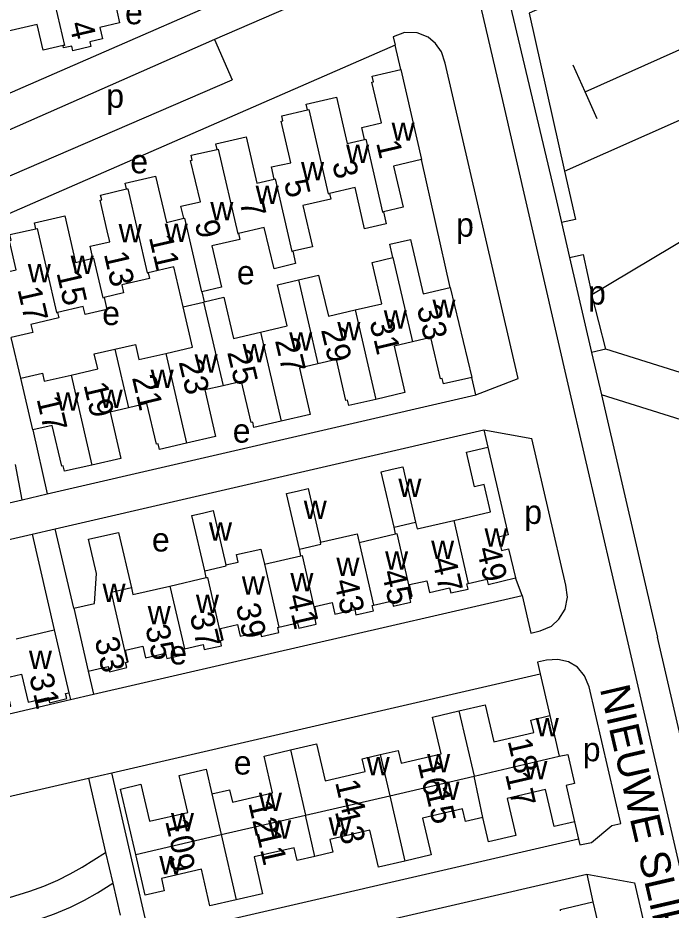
# Model space of a CAD drawing. Extents: x 155696 to 157795, y 382328 to 384028.
# Drawn here: x 157175.4 to 157284.9, y 383450.5 to 383600.1 of the extents above; entities that cross this region are included whole.
import ezdxf

# ---------------------------------------------------------------- set-up
doc = ezdxf.new("R2010")
doc.units = 0
for name, color, linetype in [('BLT_Basislijn', 7, 'Continuous'), ('BLT_Bebouwing', 7, 'Continuous'), ('BLT_Centroide', 7, 'Continuous'), ('BLT_Huisnummer', 7, 'Continuous'), ('BLT_Huisnummer_ tussenligend', 7, 'Continuous'), ('BLT_Onderverdeling_panden', 7, 'Continuous'), ('BLT_Straatnaam', 7, 'Continuous')]:
    doc.layers.add(name, color=color, linetype=linetype)

msp = doc.modelspace()

# ---------------------------------------------------------------- linework, layer by layer
at = {"layer": 'BLT_Basislijn'}
for p, q in [((157232.55, 383607.09), (157208.37, 383596.51)), ((157270.5, 383587.69), (157297.93, 383600.04)), ((157208.37, 383596.51), (157155.06, 383573.01)), ((157208.37, 383596.51), (157211.33, 383589.75)), ((157270.5, 383587.69), (157268.48, 383592.17)), ((157157.85, 383566.64), (157211.33, 383589.75)), ((157272.52, 383583.21), (157270.5, 383587.69)), ((157271.63, 383553.72), (157323.49, 383584.65)), ((157247.91, 383554.89), (157243.07, 383576.35)), ((157273.96, 383544.53), (157271.63, 383553.72)), ((157175.89, 383539.68), (157174.29, 383546.5)), ((157252.2, 383536.88), (157259.27, 383539.61)), ((157253.55, 383531.03), (157261.58, 383529.58)), ((157176.12, 383519.3), (157180.33, 383520.27)), ((157177.78, 383513.53), (157181.68, 383514.43)), ((157259.96, 383503.26), (157258.82, 383506.18)), ((157188.1, 383486.66), (157259.96, 383503.26)), ((157293.18, 383450.53), (157282.62, 383496.27)), ((157187.18, 383490.53), (157188.1, 383486.66)), ((157183.92, 383486.93), (157184.23, 383485.77)), ((157116.22, 383470.06), (157184.23, 383485.77)), ((157184.23, 383485.77), (157188.1, 383486.66)), ((157187.23, 383472.61), (157191.13, 383473.51)), ((157270.77, 383456.49), (157271.83, 383451.83))]:
    msp.add_line(p, q, dxfattribs=at)
for points in [[(157254.58, 383616.41), (157265.55, 383570.16), (157266.56, 383565.8)], [(157234.4, 383613.91), (157165.65, 383583.84), (157164.91, 383587.02)], [(157308.66, 383597.41), (157292.13, 383614.53), (157261.12, 383600.89), (157267.05, 383574.43)], [(157343.69, 383231.89), (157341.11, 383231.75), (157339.69, 383232.44), (157338.68, 383233.57), (157337.75, 383235.4), (157324.13, 383294.34), (157315.46, 383331.86), (157299.82, 383399.57), (157277.88, 383494.57), (157267.86, 383537.93), (157256.53, 383587.01), (157250.87, 383611.5)], [(157259.27, 383539.61), (157247.04, 383592.51), (157246.42, 383594.43), (157245.44, 383595.85), (157244.22, 383596.9), (157242.37, 383597.6), (157240.21, 383597.66), (157238.32, 383596.96), (157238.64, 383595.57)], [(157238.64, 383595.57), (157169.88, 383565.5), (157171.84, 383557.12)], [(157239.59, 383591.45), (157238.64, 383595.57)], [(157267.05, 383574.43), (157302.23, 383590.02), (157304.41, 383585.09), (157316.28, 383590.35)], [(157267.05, 383574.43), (157268.87, 383566.29), (157266.56, 383565.8)], [(157266.56, 383565.8), (157267.91, 383559.94)], [(157267.91, 383559.94), (157270.2, 383560.43), (157271.63, 383553.72)], [(157267.91, 383559.94), (157271.6, 383543.98)], [(157273.96, 383544.53), (157271.6, 383543.98)], [(157271.6, 383543.98), (157273.24, 383536.87)], [(157297.11, 383537.27), (157273.96, 383544.53)], [(157252.2, 383536.88), (157251.52, 383539.8)], [(157180.33, 383520.27), (157252.2, 383536.88)], [(157297.11, 383537.27), (157295.17, 383530), (157273.24, 383536.87)], [(157273.24, 383536.87), (157282.62, 383496.27)], [(157177.9, 383531.01), (157180.33, 383520.27)], [(157181.68, 383514.43), (157253.55, 383531.03)], [(157253.55, 383531.03), (157254.22, 383528.1)], [(157259.96, 383503.26), (157261.43, 383496.93), (157262.99, 383497.29), (157264.86, 383498.09), (157266.12, 383499.29), (157267.18, 383500.96), (157267.54, 383502.96), (157267.27, 383504.95), (157261.58, 383529.58)], [(157176.12, 383519.3), (157175, 383525.2)], [(157112.35, 383504.57), (157176.12, 383519.3)], [(157184.76, 383501.1), (157181.68, 383514.43)], [(157113.7, 383498.73), (157177.78, 383513.53)], [(157177.78, 383513.53), (157181.48, 383497.46)], [(157274.99, 383464.65), (157276.5, 383465), (157271.21, 383487.9), (157270.43, 383489.77), (157269.24, 383491.23), (157267.74, 383492.09), (157265.94, 383492.52), (157264.01, 383492.39), (157262.55, 383492.05), (157263, 383490.11)], [(157191.13, 383473.51), (157263, 383490.11)], [(157263, 383490.11), (157264.62, 383483.09)], [(157197.55, 383445.74), (157191.13, 383473.51)], [(157149.1, 383463.8), (157187.23, 383472.61)], [(157187.23, 383472.61), (157190.11, 383460.12)], [(157268.74, 383465.26), (157269.42, 383462.34)], [(157269.42, 383462.34), (157269.63, 383461.4), (157271.59, 383461.83), (157274.99, 383464.65)], [(157269.42, 383462.34), (157197.55, 383445.74)], [(157157.62, 383451.78), (157161.34, 383451.78), (157165.85, 383451.83), (157170.48, 383452.03), (157173.98, 383452.58), (157177.42, 383453.65), (157179.74, 383454.49), (157182.12, 383455.48), (157184.17, 383456.53), (157186.17, 383457.66), (157190.11, 383460.12)], [(157190.11, 383460.12), (157191.3, 383454.97)], [(157198.9, 383439.89), (157270.77, 383456.49)], [(157270.77, 383456.49), (157278.8, 383455.05), (157290.9, 383402.64), (157291.12, 383401.66), (157291.11, 383400.64), (157290.68, 383398.63), (157289.76, 383397.14), (157288.54, 383396.04), (157286.94, 383395.36), (157285, 383394.89), (157283.59, 383400.95)], [(157127.99, 383437.63), (157133.07, 383440.6), (157137.69, 383442.73), (157142.38, 383444.45), (157146.64, 383445.69), (157150.91, 383446.52), (157156.26, 383446.78), (157161.37, 383446.78), (157165.99, 383446.83), (157170.98, 383447.04), (157175.12, 383447.7), (157179.02, 383448.92), (157181.55, 383449.83), (157184.22, 383450.94), (157186.55, 383452.13), (157188.73, 383453.36), (157191.3, 383454.97)], [(157191.3, 383454.97), (157192.54, 383449.62)]]:
    msp.add_lwpolyline(points, dxfattribs=at)
at = {"layer": 'BLT_Bebouwing'}
for p, q in [((157239.59, 383591.45), (157243.07, 383576.35)), ((157206.26, 383554.18), (157206.65, 383552.48)), ((157247.91, 383554.89), (157251.52, 383539.8)), ((157177.9, 383531.01), (157175.89, 383539.68)), ((157250.62, 383527.27), (157254.22, 383528.1)), ((157251.97, 383521.48), (157250.62, 383527.27)), ((157236.33, 383523.99), (157238.13, 383524.41)), ((157238.13, 383524.41), (157239.94, 383524.83)), ((157239.94, 383524.83), (157242.08, 383515.53)), ((157238.48, 383514.7), (157236.33, 383523.99)), ((157222.25, 383520.74), (157224.05, 383521.16)), ((157224.05, 383521.16), (157226.13, 383512.18)), ((157253.56, 383521.84), (157251.97, 383521.48)), ((157254.62, 383517.24), (157253.56, 383521.84)), ((157220.45, 383520.33), (157222.25, 383520.74)), ((157222.6, 383511.03), (157220.45, 383520.33)), ((157204.57, 383516.66), (157206.37, 383517.07)), ((157206.72, 383507.36), (157204.57, 383516.66)), ((157206.37, 383517.07), (157208.17, 383517.49)), ((157208.17, 383517.49), (157210.28, 383508.36)), ((157248.47, 383515.81), (157254.62, 383517.24)), ((157242.08, 383515.53), (157242.34, 383514.4)), ((157242.34, 383514.4), (157248.47, 383515.81)), ((157190.49, 383513.41), (157192.29, 383513.82)), ((157192.29, 383513.82), (157194.44, 383504.54)), ((157238.74, 383513.57), (157238.48, 383514.7)), ((157187.24, 383512.66), (157190.49, 383513.41)), ((157232.6, 383512.15), (157238.74, 383513.57)), ((157222.86, 383509.9), (157222.6, 383511.03)), ((157216.73, 383508.48), (157222.86, 383509.9)), ((157200.87, 383504.82), (157206.98, 383506.23)), ((157206.98, 383506.23), (157206.72, 383507.36)), ((157194.7, 383503.39), (157200.87, 383504.82)), ((157194.44, 383504.54), (157194.7, 383503.39)), ((157184.76, 383501.1), (157187.18, 383490.53)), ((157175.09, 383495.98), (157181.48, 383497.46)), ((157181.48, 383497.46), (157183.92, 383486.93))]:
    msp.add_line(p, q, dxfattribs=at)
for points in [[(157191.64, 383602.84), (157192.46, 383599.29), (157189.16, 383598.53), (157189.61, 383596.58), (157187.46, 383596.08), (157187.64, 383595.3), (157184.62, 383594.6), (157184.44, 383595.38), (157183.07, 383595.07), (157182.98, 383595.46)], [(157182.98, 383595.46), (157179.66, 383594.69), (157178.65, 383599.02), (157172.82, 383597.68)], [(157233.52, 383579.73), (157233.07, 383581.74), (157236.35, 383582.5), (157234.77, 383589.32), (157235.04, 383589.39), (157234.81, 383590.33), (157239.59, 383591.45)], [(157223.96, 383584.69), (157223.74, 383585.64), (157228.82, 383586.84), (157230.59, 383579.05), (157233.52, 383579.73)], [(157218.39, 383573.06), (157217.9, 383575.12), (157221.18, 383575.83), (157219.55, 383582.78), (157219.82, 383582.84), (157219.63, 383583.67), (157223.96, 383584.69)], [(157208.79, 383578.07), (157208.57, 383579.02), (157213.65, 383580.19), (157215.44, 383572.39), (157218.39, 383573.06)], [(157203.21, 383566.51), (157202.73, 383568.54), (157206.03, 383569.24), (157204.37, 383576.18), (157204.65, 383576.24), (157204.45, 383577.07), (157208.79, 383578.07)], [(157243.07, 383576.35), (157238.39, 383575.27), (157239.99, 383568.35), (157236.7, 383567.59)], [(157193.61, 383571.42), (157193.38, 383572.38), (157198.46, 383573.59), (157200.3, 383565.82), (157203.21, 383566.51)], [(157187.99, 383559.79), (157187.52, 383561.83), (157190.82, 383562.57), (157190.38, 383564.42), (157189.17, 383569.52), (157189.45, 383569.58), (157189.26, 383570.41), (157193.61, 383571.42)], [(157227.63, 383570.67), (157227.85, 383569.72), (157223.2, 383568.65), (157224.79, 383561.73), (157221.5, 383560.97)], [(157236.7, 383567.59), (157237.17, 383565.58), (157233.53, 383564.74), (157231.94, 383571.66), (157227.63, 383570.67)], [(157178.4, 383564.76), (157178.18, 383565.72), (157183.26, 383566.89), (157184.15, 383563)], [(157171.84, 383557.12), (157175.12, 383557.87), (157174, 383562.75), (157174.25, 383562.82), (157174.05, 383563.77), (157178.4, 383564.76)], [(157221.5, 383560.97), (157221.97, 383558.93), (157218.36, 383558.02), (157216.68, 383564.94), (157212.38, 383563.93)], [(157184.15, 383563), (157185.05, 383559.11), (157187.99, 383559.79)], [(157212.38, 383563.93), (157212.6, 383562.96), (157207.93, 383561.86), (157209.56, 383554.95), (157206.26, 383554.18)], [(157238.29, 383559.92), (157237.77, 383562.18), (157241.21, 383562.97), (157243.33, 383553.81), (157247.91, 383554.89)], [(157231.95, 383551.14), (157236.41, 383552.18), (157234.79, 383559.1), (157238.29, 383559.92)], [(157197.27, 383557.37), (157197.49, 383556.42), (157192.82, 383555.34), (157193.13, 383553.98), (157189.85, 383553.22)], [(157203.11, 383551.66), (157201.56, 383558.38), (157197.27, 383557.37)], [(157216.09, 383547.41), (157220.54, 383548.45), (157218.91, 383555.36), (157222.43, 383556.19)], [(157222.43, 383556.19), (157225.83, 383556.99), (157227.46, 383550.08), (157231.95, 383551.14)], [(157189.85, 383553.22), (157190.32, 383551.2), (157186.68, 383550.36), (157186.37, 383551.73), (157182.06, 383550.73)], [(157206.65, 383552.48), (157209.95, 383553.26), (157211.58, 383546.35), (157216.09, 383547.41)], [(157200.2, 383543.85), (157204.67, 383544.88), (157203.11, 383551.66)], [(157182.06, 383550.73), (157182.28, 383549.78), (157177.6, 383548.7), (157177.92, 383547.33), (157174.29, 383546.5)], [(157191.65, 383544.55), (157195.12, 383545.35), (157195.7, 383542.82), (157200.2, 383543.85)], [(157241.54, 383545.76), (157238.51, 383545.04), (157240.3, 383537.26), (157235.43, 383536.13)], [(157251.52, 383539.8), (157246.74, 383538.73), (157246.53, 383539.65), (157246.27, 383539.59), (157244.66, 383546.49), (157241.54, 383545.76)], [(157184.32, 383540.19), (157188.79, 383541.23), (157188.2, 383543.75), (157191.65, 383544.55)], [(157225.69, 383542.08), (157222.6, 383541.36), (157224.4, 383533.59), (157219.53, 383532.46)], [(157235.43, 383536.13), (157230.88, 383535.08), (157230.67, 383536), (157230.4, 383535.94), (157228.82, 383542.81), (157225.69, 383542.08)], [(157175.89, 383539.68), (157179.52, 383540.52), (157179.83, 383539.16), (157184.32, 383540.19)], [(157219.53, 383532.46), (157214.99, 383531.41), (157214.77, 383532.33), (157214.51, 383532.27), (157212.92, 383539.14), (157209.82, 383538.42)], [(157209.82, 383538.42), (157206.74, 383537.71), (157208.55, 383529.93), (157203.68, 383528.8)], [(157193.93, 383534.72), (157190.86, 383534.01), (157192.66, 383526.24), (157187.79, 383525.12)], [(157203.68, 383528.8), (157199.12, 383527.74), (157198.9, 383528.65), (157198.64, 383528.59), (157197.05, 383535.45), (157193.93, 383534.72)], [(157187.79, 383525.12), (157183.24, 383524.07), (157183.01, 383525.01), (157182.75, 383524.95), (157181.15, 383531.77), (157177.9, 383531.01)], [(157254.22, 383528.1), (157257.61, 383513.4), (157255.96, 383513.01), (157256.47, 383510.76), (157257.64, 383511.04), (157258.82, 383506.18)], [(157184.76, 383501.1), (157188.25, 383501.87), (157188.56, 383506.91), (157187.24, 383512.66)], [(157226.13, 383512.18), (157232.3, 383513.6), (157232.6, 383512.15)], [(157210.28, 383508.36), (157212.35, 383508.83), (157212.06, 383510.09), (157216.12, 383511.01), (157216.73, 383508.48)], [(157250.91, 383505.24), (157254.05, 383505.98), (157254.23, 383505.1), (157258.82, 383506.18)], [(157241.35, 383503.05), (157241.53, 383503.1), (157241.09, 383505.05), (157243.96, 383505.7), (157244.41, 383503.75), (157247.77, 383504.52), (157247.99, 383503.66), (157250.9, 383504.32), (157250.7, 383505.2), (157250.91, 383505.24)], [(157225.48, 383499.38), (157225.66, 383499.43), (157225.21, 383501.38), (157228.09, 383502.04), (157228.54, 383500.1), (157231.88, 383500.87), (157232.08, 383499.99), (157235.02, 383500.67), (157234.82, 383501.54), (157235.04, 383501.59)], [(157235.04, 383501.59), (157238.19, 383502.32), (157238.34, 383501.44), (157241.28, 383502.11), (157241.08, 383502.99), (157241.35, 383503.05)], [(157219.18, 383497.93), (157222.3, 383498.65), (157222.51, 383497.78), (157225.44, 383498.45), (157225.24, 383499.33), (157225.48, 383499.38)], [(157209.62, 383495.72), (157209.81, 383495.77), (157209.36, 383497.72), (157212.21, 383498.37), (157212.66, 383496.42), (157216.03, 383497.2), (157216.24, 383496.33), (157219.16, 383497), (157218.96, 383497.88), (157219.18, 383497.93)], [(157203.32, 383494.28), (157206.44, 383495.03), (157206.63, 383494.15), (157209.56, 383494.79), (157209.37, 383495.67), (157209.62, 383495.72)], [(157193.74, 383492.07), (157193.89, 383492.11), (157193.43, 383494.05), (157196.34, 383494.71), (157196.8, 383492.76), (157200.16, 383493.55), (157200.36, 383492.67), (157203.28, 383493.35), (157203.08, 383494.23), (157203.32, 383494.28)], [(157187.18, 383490.53), (157190.53, 383491.32), (157190.74, 383490.44), (157193.67, 383491.13), (157193.46, 383492.01), (157193.74, 383492.07)], [(157174.04, 383484.65), (157174.21, 383484.68), (157173.15, 383489.36), (157176.03, 383490.03), (157177.11, 383485.36), (157180.52, 383486.14), (157180.7, 383485.25), (157183.61, 383485.93), (157183.41, 383486.81), (157183.92, 383486.93)], [(157236.15, 383476.55), (157239.16, 383477.25), (157239.65, 383475.1), (157246.36, 383476.65), (157244.93, 383482.85), (157249.34, 383483.87)], [(157249.34, 383483.87), (157253.75, 383484.89), (157255.19, 383478.69), (157261.9, 383480.24), (157261.41, 383482.34), (157264.62, 383483.09)], [(157264.62, 383483.09), (157266.18, 383476.31)], [(157221.09, 383477.34), (157225.48, 383478.36), (157226.93, 383472.16), (157233.64, 383473.71), (157233.15, 383475.86), (157236.15, 383476.55)], [(157207.9, 383469.97), (157210.9, 383470.66), (157211.38, 383468.57), (157218.11, 383470.12), (157216.67, 383476.31), (157221.09, 383477.34)], [(157266.18, 383476.31), (157267.62, 383476.55), (157268.74, 383471.69), (157267.32, 383471.36), (157268.74, 383465.26)], [(157195.16, 383459.81), (157192.63, 383470.77), (157196.03, 383471.56), (157197.46, 383465.36), (157203.89, 383466.85), (157202.46, 383473.04), (157206.96, 383474.08), (157207.9, 383469.97)], [(157268.74, 383465.26), (157265.31, 383464.47), (157263.88, 383470.67), (157257.45, 383469.19), (157258.88, 383462.98), (157254.31, 383461.93), (157253.37, 383465.99)], [(157253.37, 383465.99), (157250.46, 383465.31), (157249.97, 383467.46), (157243.26, 383465.91), (157244.68, 383459.71), (157240.28, 383458.69)], [(157240.28, 383458.69), (157235.87, 383457.67), (157234.43, 383463.87), (157227.72, 383462.32), (157228.22, 383460.18), (157225.21, 383459.48)], [(157212.01, 383452.17), (157207.61, 383451.16), (157206.18, 383457.34), (157199.47, 383455.79), (157199.95, 383453.69), (157196.73, 383452.95), (157195.16, 383459.81)], [(157225.21, 383459.48), (157222.21, 383458.79), (157221.71, 383460.93), (157215, 383459.38), (157216.42, 383453.19), (157212.01, 383452.17)], [(157266.4, 383450.35), (157266.36, 383450.56), (157271.83, 383451.83)], [(157271.83, 383451.83), (157273.57, 383444.31), (157274.68, 383444.57), (157275.51, 383440.95), (157274.4, 383440.7), (157274.59, 383439.93)]]:
    msp.add_lwpolyline(points, dxfattribs=at)
at = {"layer": 'BLT_Onderverdeling_panden'}
for p, q in [((157238.29, 383559.92), (157241.54, 383545.76)), ((157222.43, 383556.19), (157225.69, 383542.08)), ((157203.11, 383551.66), (157206.54, 383552.45)), ((157206.54, 383552.45), (157206.65, 383552.48)), ((157206.54, 383552.45), (157209.82, 383538.42)), ((157231.95, 383551.14), (157235.43, 383536.13)), ((157216.09, 383547.41), (157219.53, 383532.46)), ((157191.65, 383544.55), (157193.93, 383534.72)), ((157200.2, 383543.85), (157203.68, 383528.8)), ((157184.32, 383540.19), (157187.79, 383525.12)), ((157238.48, 383514.7), (157242.08, 383515.53)), ((157248.47, 383515.81), (157250.91, 383505.24)), ((157232.6, 383512.15), (157235.04, 383501.59)), ((157216.73, 383508.48), (157219.18, 383497.93)), ((157200.87, 383504.82), (157203.32, 383494.28)), ((157249.34, 383483.87), (157251.88, 383472.91)), ((157221.09, 383477.34), (157223.62, 383466.38)), ((157236.15, 383476.55), (157237.75, 383469.65)), ((157251.88, 383472.91), (157266.18, 383476.31)), ((157237.75, 383469.65), (157251.88, 383472.91)), ((157253.37, 383465.99), (157251.88, 383472.91)), ((157207.9, 383469.97), (157209.49, 383463.12)), ((157237.75, 383469.65), (157240.28, 383458.69)), ((157225.21, 383459.48), (157223.62, 383466.38)), ((157195.16, 383459.81), (157209.49, 383463.12)), ((157209.49, 383463.12), (157212.01, 383452.17))]:
    msp.add_line(p, q, dxfattribs=at)
for points in [[(157181.08, 383605.64), (157180.87, 383605.59), (157183.2, 383595.51), (157182.98, 383595.46)], [(157223.96, 383584.69), (157224.19, 383584.74), (157227.44, 383570.62), (157227.63, 383570.67)], [(157233.52, 383579.73), (157233.72, 383579.78), (157236.51, 383567.55), (157236.7, 383567.59)], [(157208.79, 383578.07), (157209.01, 383578.12), (157212.28, 383563.9), (157212.38, 383563.93)], [(157218.39, 383573.06), (157218.53, 383573.1), (157221.32, 383560.93), (157221.5, 383560.97)], [(157193.61, 383571.42), (157193.82, 383571.47), (157197.09, 383557.33), (157197.27, 383557.37)], [(157203.21, 383566.51), (157203.32, 383566.54), (157206.17, 383554.16), (157206.26, 383554.18)], [(157178.4, 383564.76), (157178.63, 383564.81), (157181.89, 383550.69), (157182.06, 383550.73)], [(157187.99, 383559.79), (157188.1, 383559.82), (157189.64, 383553.17), (157189.85, 383553.22)], [(157238.74, 383513.57), (157238.92, 383513.61), (157241.35, 383503.05)], [(157222.6, 383511.03), (157226.2, 383511.86), (157226.13, 383512.18)], [(157222.86, 383509.9), (157223.04, 383509.94), (157225.48, 383499.38)], [(157206.72, 383507.36), (157210.32, 383508.19), (157210.28, 383508.36)], [(157206.98, 383506.23), (157207.18, 383506.28), (157209.62, 383495.72)], [(157194.44, 383504.54), (157191.03, 383503.74)], [(157191.03, 383503.74), (157193.74, 383492.07)], [(157223.62, 383466.38), (157237.75, 383469.65)], [(157209.49, 383463.12), (157223.62, 383466.38)]]:
    msp.add_lwpolyline(points, dxfattribs=at)

# ---------------------------------------------------------------- texts
at = {"layer": 'BLT_Centroide'}
for s, p in [('e', (157193.37, 383599.05)), ('p', (157190.23, 383585.04)), ('w', (157238.06, 383579.5)), ('w', (157230.44, 383575.78)), ('e', (157194.25, 383574.05)), ('w', (157222.88, 383572.86)), ('w', (157215.27, 383568.88)), ('w', (157207.67, 383566.16)), ('p', (157248.88, 383563.42)), ('w', (157192.3, 383562.45)), ('w', (157200.02, 383562.53)), ('w', (157184.25, 383557.14)), ('w', (157177.06, 383555.78)), ('e', (157212.12, 383555.42)), ('p', (157271.01, 383552.03)), ('w', (157244.91, 383549.81)), ('e', (157189.54, 383548.59)), ('w', (157236.75, 383548)), ('w', (157228.96, 383546.03)), ('w', (157220.89, 383544.31)), ('w', (157213.08, 383542.34)), ('w', (157205.02, 383540.61)), ('w', (157197.66, 383538.05)), ('w', (157189.12, 383534.7)), ('w', (157181.84, 383534.22)), ('e', (157211.43, 383528.87)), ('w', (157239.2, 383519.77)), ('w', (157223.33, 383516.09)), ('p', (157260.31, 383515.24)), ('w', (157207.44, 383512.42)), ('e', (157197.88, 383510.61)), ('w', (157253.64, 383511.44)), ('w', (157244.69, 383509.38)), ('w', (157236.97, 383507.59)), ('w', (157228.81, 383506.48)), ('w', (157212.95, 383503.39)), ('w', (157221.09, 383503.94)), ('w', (157189.59, 383502.14)), ('w', (157205.25, 383500.3)), ('w', (157197.17, 383498.41)), ('e', (157200.79, 383491.67)), ('w', (157177.25, 383490.92)), ('w', (157262.23, 383479.59)), ('p', (157270.12, 383475.43)), ('e', (157211.6, 383473.2)), ('w', (157244.02, 383473.59)), ('w', (157233.88, 383473.06)), ('w', (157260.31, 383472.38)), ('w', (157245.56, 383468.94)), ('w', (157215.81, 383467.09)), ('w', (157201.06, 383463.69)), ('w', (157227.49, 383462.97)), ('w', (157217.36, 383462.44)), ('w', (157199.12, 383456.44))]:
    msp.add_text(s, height=4, dxfattribs=at).set_placement(p)
at = {"layer": 'BLT_Huisnummer'}
for s, rotation, p in [('1', 283.0065, (157235.45, 383579.18)), ('5', 283.0065, (157219.99, 383572.59)), ('9', 283.0065, (157205.03, 383565.76)), ('13', 283.0065, (157189.79, 383560.53)), ('17', 283.0065, (157175.31, 383554.59)), ('33', 283.2889, (157242.26, 383551.56)), ('29', 283.2889, (157226.2, 383547.81)), ('25', 283.2889, (157210.47, 383544.05)), ('21', 283.2889, (157194.51, 383539.79)), ('17', 283.2889, (157178.51, 383536.21)), ('49', 283.0042, (157252.31, 383511.03)), ('45', 283.0042, (157236.35, 383507.16)), ('41', 283.0042, (157220.5, 383503.12)), ('37', 283.0042, (157204.19, 383499.96)), ('33', 283.0042, (157188.24, 383495.83)), ('31', 283.0042, (157177.27, 383489.73)), ('18', 283.006, (157257.49, 383478.86)), ('17', 283.0058, (157257.08, 383473.26)), ('14', 283.006, (157228.57, 383471.93)), ('13', 283.0058, (157228.53, 383467.01)), ('10', 283.006, (157200.08, 383465.41)), ('9', 283.0058, (157200.69, 383459.44))]:
    msp.add_text(s, height=4, rotation=rotation, dxfattribs=at).set_placement(p)
at = {"layer": 'BLT_Huisnummer_ tussenligend'}
for s, rotation, p in [('4', 283.0063, (157183.98, 383599.14)), ('3', 283.0065, (157228.07, 383575.76)), ('7', 283.0065, (157212.56, 383569.26)), ('11', 283.0065, (157197.35, 383563.33)), ('15', 283.0065, (157181.85, 383557.37)), ('31', 283.2889, (157234.32, 383549.17)), ('27', 283.2889, (157218.48, 383546.02)), ('23', 283.2889, (157202.34, 383542.43)), ('19', 283.2889, (157186.38, 383538.59)), ('47', 283.0042, (157244.84, 383509.23)), ('43', 283.0042, (157228.38, 383505.61)), ('39', 283.0042, (157211.91, 383501.5)), ('35', 283.0042, (157196.73, 383497.89)), ('16', 283.006, (157242.39, 383475.18)), ('15', 283.0058, (157243.69, 383470.42)), ('12', 283.006, (157214.01, 383468.45)), ('11', 283.0058, (157215.33, 383463.54))]:
    msp.add_text(s, height=4, rotation=rotation, dxfattribs=at).set_placement(p)
at = {"layer": 'BLT_Straatnaam'}
msp.add_text('NIEUWE SLIFFERTSESTRAAT', height=5, rotation=283.0066, dxfattribs=at).set_placement((157272.96, 383487.62))

doc.saveas('drawing.dxf')
